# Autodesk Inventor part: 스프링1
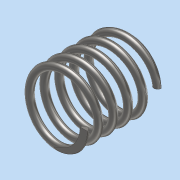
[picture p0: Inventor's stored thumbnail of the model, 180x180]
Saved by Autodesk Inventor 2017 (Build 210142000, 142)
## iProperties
Part Number: 스프링1
Material: 스테인레스 스틸
Document SubType Name: Modeling
Designer: MRC
Density: 8 g/cm^3
Appearance: 반연마
Mass: 6.57569 g
Surface Area: 16.7185 cm^2
Volume: 0.821961 cm^3
Author: MRC
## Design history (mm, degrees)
sketch "스케치1"
  geometry: L1 (0, 0)-(0, 20.5); L2 (0, 0)-(8.5, 0); L3 (0, 20.5)-(8.5, 20.5); C1 r 1 at (8.5, 0)
  constraints: 6 end point, 1 centre point, 1 coincident, 1 horizontal, 1 vertical, 1 vertical alignment
  dimensions: "d0" = 20.5 distance of L1.start L1.end (derived); "d1" = 17 diameter of L2.end L1; "d2" = 2 diameter of C1
feature "코일1" pitch "d3" = 10; turns "d5" = 5; dims "d4" = 20.5 (= d0), "d6" = 0, angle "d7" = 90 deg, angle "d8" = 90 deg, "d9" = 0, "d10" = 0
sketch "스케치2"
  geometry: L1 (20.5, 17.5)-(0, 17.5); L2 (0, 17.5)-(0, -17.5); L3 (0, -17.5)-(20.5, -17.5); L4 (20.5, -17.5)-(20.5, 17.5); 2 further points
  constraints: 8 end point, 2 parallel, 1 coincident, 1 horizontal, 1 midpoint, 1 perpendicular
  dimensions: "d11" = 20.5 distance of L2.end L3.end (= d0); "d12" = 35 distance between parallel lines of L1 L3
extrude "돌출2" sketch "스케치2" stored distance "d15" = 0; taper "d16" = 0 deg
node "솔리드1"
